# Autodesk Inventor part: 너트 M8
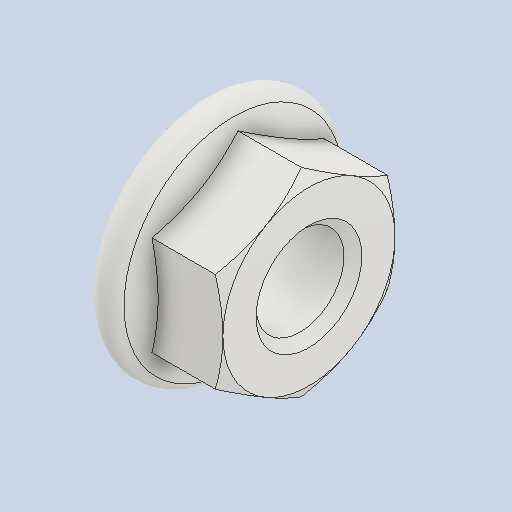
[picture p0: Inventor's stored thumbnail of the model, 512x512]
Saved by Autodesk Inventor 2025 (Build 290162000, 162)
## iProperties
Created: 2024-07
Part Number: 너트 M8
Material: 스테인리스강
Description: 플랜지붙이 6각 너트 - 일반 스레드
Document SubType Name: Modeling
Designer: anfro
Density: 8 g/cm^3
Appearance: 기본값
Author: jhkim
Sending System: Autodesk Inventor 2025
Preprocessor: ST-DEVELOPER v20
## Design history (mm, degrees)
feature "Solid1"
node "솔리드1"
